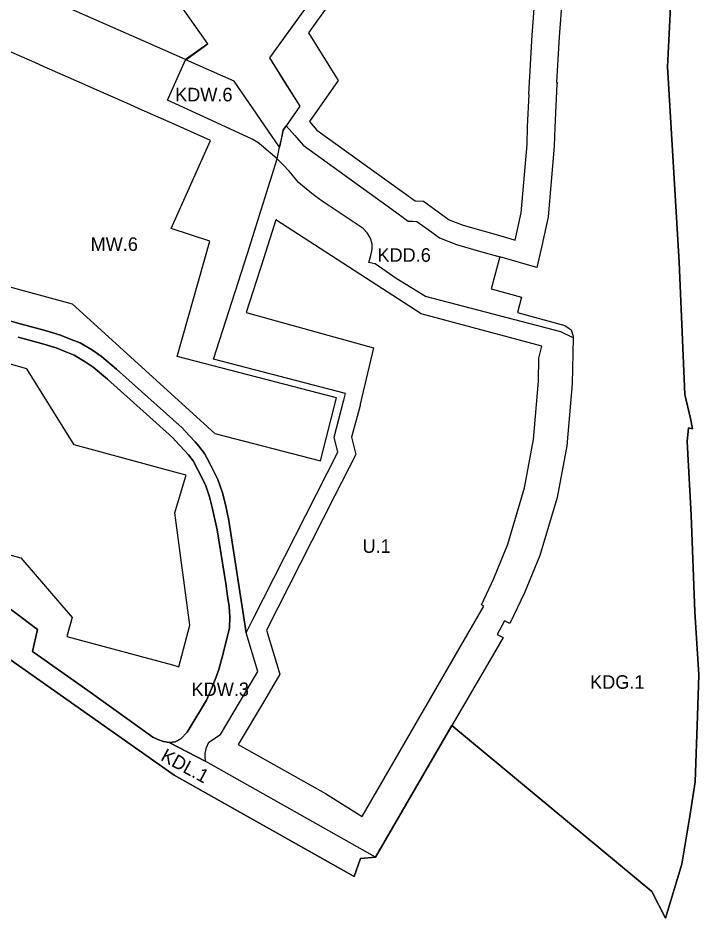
# Model space of a CAD drawing. Extents: x 7432050 to 7433361, y 5551438 to 5552391.
# Drawn here: x 7432993.3 to 7433194.3, y 5551437.6 to 5551703.3 of the extents above; entities that cross this region are included whole.
import ezdxf

# ---------------------------------------------------------------- set-up
doc = ezdxf.new("R2010")
doc.units = 0
for name, color, linetype in [('granica planu', 7, 'Continuous'), ('linie rozgraniczające', 7, 'Continuous'), ('MPZP_Niebyla_Na_Wzgorzach', 7, 'Continuous'), ('nieprzekraczalne linie zabudowy', 7, 'Continuous'), ('oznaczenia przeznaczen', 7, 'Continuous')]:
    doc.layers.add(name, color=color, linetype=linetype)

msp = doc.modelspace()

# ---------------------------------------------------------------- linework, layer by layer
at = {"layer": 'granica planu'}
for p, q in [((7433092.47, 5551449.86), (7433039.39, 5551479.73)), ((7433189.28, 5551453.42), (7433184.41, 5551437.57))]:
    msp.add_line(p, q, dxfattribs=at)
for points in [[(7433186.18, 5551712.56), (7433185.05, 5551688.87), (7433188.47, 5551631.14), (7433190.16, 5551592.1), (7433191.79, 5551585.02), (7433192.43, 5551582.03), (7433191.23, 5551582.31), (7433190.83, 5551578.25), (7433191.96, 5551556.49), (7433193.11, 5551528), (7433194.31, 5551509.38), (7433193.87, 5551497.26), (7433193.22, 5551477.78), (7433191.57, 5551467.67), (7433189.28, 5551453.42)], [(7433039.39, 5551479.73), (7432960, 5551535.68), (7432943.56, 5551546.17), (7432893.1, 5551557.41)], [(7433121.39, 5551494.42), (7433098.78, 5551455.56), (7433094.4, 5551455.09), (7433092.47, 5551449.86)], [(7433184.41, 5551437.57), (7433180.36, 5551445.41), (7433121.39, 5551494.42)]]:
    msp.add_lwpolyline(points, dxfattribs=at)
at = {"layer": 'linie rozgraniczające'}
for p, q in [((7433026.86, 5551698), (7432950.78, 5551731.59)), ((7433154.12, 5551712.23), (7433153.02, 5551697.71)), ((7433042.75, 5551690.98), (7433026.86, 5551698)), ((7433049.29, 5551695.66), (7433042.75, 5551690.98)), ((7433152.31, 5551683.72), (7433151.71, 5551670.92)), ((7433152.6, 5551683.99), (7433152.31, 5551683.72)), ((7433151.71, 5551670.92), (7433151.53, 5551665.42)), ((7433060.99, 5551633.72), (7433069.8, 5551661.73)), ((7433076.05, 5551654.73), (7433074.82, 5551656.24)), ((7433077.82, 5551653.26), (7433076.05, 5551654.73)), ((7433079.38, 5551651.96), (7433077.82, 5551653.26)), ((7433080.94, 5551650.8), (7433079.38, 5551651.96)), ((7433096.32, 5551639.83), (7433095.21, 5551641.09)), ((7433097.34, 5551638.24), (7433096.32, 5551639.83)), ((7433051, 5551602.59), (7433060.99, 5551633.72)), ((7433098.67, 5551630.66), (7433098.65, 5551630.67)), ((7432994.34, 5551612.91), (7432980.9, 5551616.6)), ((7433008.93, 5551608.38), (7433005.84, 5551609.68)), ((7432993.28, 5551609.06), (7433000.17, 5551607.16)), ((7433011.6, 5551607.34), (7433008.93, 5551608.38)), ((7433015.28, 5551605.17), (7433011.6, 5551607.34)), ((7433013.12, 5551601.8), (7433015.46, 5551600.16)), ((7433089.94, 5551592.45), (7433051, 5551602.59)), ((7433089.94, 5551592.45), (7433051, 5551602.59)), ((7433089.47, 5551590.44), (7433089.94, 5551592.45)), ((7433191.79, 5551585.02), (7433190.16, 5551592.1)), ((7433086.61, 5551579.57), (7433089.4, 5551590.14)), ((7433089.4, 5551590.14), (7433089.47, 5551590.44)), ((7433038.92, 5551579.39), (7433040.89, 5551577.29)), ((7433087.7, 5551575.06), (7433086.61, 5551579.57)), ((7433062.58, 5551525.7), (7433087.7, 5551575.06)), ((7433046.44, 5551569.67), (7433048.59, 5551565.44)), ((7433048.59, 5551565.44), (7433049.82, 5551561.88)), ((7433049.82, 5551561.88), (7433050.64, 5551558.74)), ((7433054.53, 5551559.68), (7433053.65, 5551563.05)), ((7433194.31, 5551509.38), (7433193.11, 5551528)), ((7433060.6, 5551521.71), (7433062.58, 5551525.7)), ((7433055.75, 5551523.17), (7433053.59, 5551514.58)), ((7433193.87, 5551497.26), (7433194.31, 5551509.38)), ((7433193.22, 5551477.78), (7433193.87, 5551497.26)), ((7433098.78, 5551455.56), (7433121.39, 5551494.42)), ((7433121.39, 5551494.42), (7433180.36, 5551445.41)), ((7433039.69, 5551489.62), (7433037.91, 5551489.39)), ((7433037.91, 5551489.39), (7433048.73, 5551483.76)), ((7433098.78, 5551455.56), (7433048.73, 5551483.76)), ((7433039.39, 5551479.73), (7433092.47, 5551449.86)), ((7433092.47, 5551449.86), (7433039.39, 5551479.73)), ((7433191.57, 5551467.67), (7433193.22, 5551477.78)), ((7433189.28, 5551453.42), (7433191.57, 5551467.67)), ((7433094.4, 5551455.09), (7433098.78, 5551455.56)), ((7433092.47, 5551449.86), (7433094.4, 5551455.09)), ((7433184.41, 5551437.57), (7433189.28, 5551453.42)), ((7433189.28, 5551453.42), (7433184.41, 5551437.57)), ((7433180.36, 5551445.41), (7433184.41, 5551437.57))]:
    msp.add_line(p, q, dxfattribs=at)
for points in [[(7433081.21, 5551710.55), (7433074.38, 5551701.03), (7433067.54, 5551691.5), (7433071.99, 5551684.37), (7433076.44, 5551677.23), (7433074.46, 5551674.35), (7433072.47, 5551671.47), (7433074.96, 5551668.6), (7433077.45, 5551665.73), (7433088.07, 5551658.07), (7433098.69, 5551650.41), (7433103.59, 5551646.87), (7433108.5, 5551643.33), (7433109.74, 5551643.29), (7433110.97, 5551643.24), (7433114.33, 5551640.82), (7433117.7, 5551638.4), (7433122.77, 5551636.39), (7433129.14, 5551634.58), (7433135.51, 5551632.77)], [(7433190.16, 5551592.1), (7433188.47, 5551631.14), (7433185.05, 5551688.87), (7433186.18, 5551712.56)], [(7433186.18, 5551712.56), (7433185.05, 5551688.87), (7433188.47, 5551631.14), (7433190.16, 5551592.1), (7433191.79, 5551585.02), (7433192.43, 5551582.03), (7433191.23, 5551582.31), (7433190.83, 5551578.25), (7433191.96, 5551556.49), (7433193.11, 5551528), (7433194.31, 5551509.38), (7433193.87, 5551497.26), (7433193.22, 5551477.78), (7433191.57, 5551467.67), (7433189.28, 5551453.42)], [(7433153.02, 5551697.71), (7433152.25, 5551684.29), (7433152.6, 5551683.99)], [(7433069.8, 5551661.73), (7433065.19, 5551665.62), (7433064.12, 5551666.51), (7433062.45, 5551667.48), (7433048.15, 5551674.07), (7433037.43, 5551679.01), (7433042.69, 5551690.94), (7433042.75, 5551690.98)], [(7433069.8, 5551661.73), (7433070.5, 5551665.12), (7433071.02, 5551667.62), (7433071.53, 5551670.11), (7433072.47, 5551671.47)], [(7433151.53, 5551665.42), (7433149.77, 5551644.59), (7433147.89, 5551636.05), (7433146.48, 5551629.66), (7433135.51, 5551632.77)], [(7433074.82, 5551656.24), (7433073.29, 5551658.08), (7433071.54, 5551659.91), (7433069.8, 5551661.73)], [(7433095.21, 5551641.09), (7433083.08, 5551649.19), (7433080.94, 5551650.8)], [(7433097.39, 5551633.18), (7433097.63, 5551634), (7433097.82, 5551635.07), (7433097.78, 5551636.54), (7433097.34, 5551638.24)], [(7433098.65, 5551630.67), (7433096.83, 5551631.11), (7433097.39, 5551633.18)], [(7433157.12, 5551608.89), (7433153.55, 5551610.6), (7433113.55, 5551621.04), (7433104.95, 5551626.37), (7433098.67, 5551630.66)], [(7433135.51, 5551632.77), (7433132.95, 5551623.34), (7433141.95, 5551620.87), (7433140.71, 5551616.3), (7433154.73, 5551612.51), (7433156.54, 5551611.23), (7433157.13, 5551609.38), (7433157.12, 5551608.89), (7433156.87, 5551595.23)], [(7432980.9, 5551616.6), (7432994.34, 5551612.91), (7433001.26, 5551611.01), (7433005.84, 5551609.68), (7433008.93, 5551608.38), (7433011.6, 5551607.34), (7433015.28, 5551605.17), (7433017.89, 5551603.34), (7433022.35, 5551599.63), (7433041.72, 5551582.26), (7433043.83, 5551580.01), (7433045.56, 5551578.11), (7433046.69, 5551576.86), (7433048.33, 5551574.66), (7433049.99, 5551571.51), (7433052.28, 5551567.01), (7433053.65, 5551563.05), (7433054.53, 5551559.68), (7433055.54, 5551554.94), (7433060.6, 5551521.71)], [(7433005.84, 5551609.68), (7433001.26, 5551611.01), (7432994.34, 5551612.91)], [(7433055.75, 5551523.17), (7433055.8, 5551526.46), (7433055.62, 5551529.51), (7433055.14, 5551532.55), (7433054.65, 5551536.34), (7433052.1, 5551552.18), (7433050.64, 5551558.74), (7433049.82, 5551561.88), (7433048.59, 5551565.44), (7433046.44, 5551569.67), (7433044.94, 5551572.52), (7433043.59, 5551574.32), (7433042.6, 5551575.42), (7433040.89, 5551577.29), (7433038.92, 5551579.39), (7433019.73, 5551596.6), (7433015.46, 5551600.16), (7433013.12, 5551601.8), (7433009.84, 5551603.73), (7433007.43, 5551604.68), (7433004.5, 5551605.9), (7433000.17, 5551607.16), (7432993.28, 5551609.06)], [(7433000.17, 5551607.16), (7433004.5, 5551605.9), (7433007.43, 5551604.68), (7433009.84, 5551603.73), (7433013.12, 5551601.8)], [(7433049.99, 5551571.51), (7433048.33, 5551574.66), (7433046.69, 5551576.86), (7433045.56, 5551578.11), (7433043.83, 5551580.01), (7433041.72, 5551582.26), (7433022.35, 5551599.63), (7433017.89, 5551603.34), (7433015.28, 5551605.17)], [(7433015.46, 5551600.16), (7433019.73, 5551596.6), (7433038.92, 5551579.39)], [(7433156.87, 5551595.23), (7433155.32, 5551577), (7433152.41, 5551561.71), (7433147.28, 5551544.57), (7433142.75, 5551533.54), (7433138.51, 5551524.5), (7433136.93, 5551525.32), (7433134.74, 5551521.23), (7433136.5, 5551520.39), (7433132.55, 5551513.6), (7433121.39, 5551494.42)], [(7433193.11, 5551528), (7433191.96, 5551556.49), (7433190.83, 5551578.25), (7433191.23, 5551582.31), (7433192.43, 5551582.03), (7433191.79, 5551585.02)], [(7433040.89, 5551577.29), (7433042.6, 5551575.42), (7433043.59, 5551574.32), (7433044.94, 5551572.52), (7433046.44, 5551569.67)], [(7433053.65, 5551563.05), (7433052.28, 5551567.01), (7433049.99, 5551571.51)], [(7433060.6, 5551521.71), (7433055.54, 5551554.94), (7433054.53, 5551559.68)], [(7433039.39, 5551479.73), (7432960, 5551535.68), (7432943.56, 5551546.17), (7432893.1, 5551557.41)], [(7433050.64, 5551558.74), (7433052.1, 5551552.18), (7433054.65, 5551536.34)], [(7432943.56, 5551546.17), (7432960, 5551535.68), (7433039.39, 5551479.73)], [(7432957.13, 5551544.64), (7432960.96, 5551542.08), (7432969.46, 5551544.99), (7432999.04, 5551522.76)], [(7432999.04, 5551522.76), (7432969.46, 5551544.99), (7432960.96, 5551542.08), (7432957.13, 5551544.64)], [(7433054.65, 5551536.34), (7433055.14, 5551532.55), (7433055.62, 5551529.51), (7433055.8, 5551526.46), (7433055.75, 5551523.17)], [(7432999.04, 5551522.76), (7432997.6, 5551516.25), (7433013.93, 5551504.72), (7433033.12, 5551490.99)], [(7433033.12, 5551490.99), (7433013.93, 5551504.72), (7432997.6, 5551516.25), (7432999.04, 5551522.76)], [(7433037.91, 5551489.39), (7433039.69, 5551489.62), (7433041.38, 5551490.42), (7433043.17, 5551492.4), (7433043.67, 5551493.23), (7433048.89, 5551501.92), (7433050.35, 5551505.27), (7433051.72, 5551508.51), (7433052.54, 5551510.94), (7433053.59, 5551514.58), (7433055.75, 5551523.17)], [(7433048.73, 5551483.76), (7433048.51, 5551484.89), (7433048.52, 5551486.14), (7433048.96, 5551487.91), (7433049.57, 5551489.5), (7433053.08, 5551491.73), (7433060.85, 5551504.87), (7433064.09, 5551510.36), (7433060.6, 5551521.71)], [(7433053.59, 5551514.58), (7433052.54, 5551510.94), (7433051.72, 5551508.51)], [(7433051.72, 5551508.51), (7433050.35, 5551505.27), (7433048.89, 5551501.92)], [(7433048.89, 5551501.92), (7433043.67, 5551493.23), (7433043.17, 5551492.4)], [(7433121.39, 5551494.42), (7433098.78, 5551455.56), (7433094.4, 5551455.09), (7433092.47, 5551449.86)], [(7433184.41, 5551437.57), (7433180.36, 5551445.41), (7433121.39, 5551494.42)], [(7433033.12, 5551490.99), (7433034.51, 5551490.31), (7433036.18, 5551489.67), (7433037.91, 5551489.39)], [(7433048.73, 5551483.76), (7433037.91, 5551489.39), (7433036.18, 5551489.67), (7433034.51, 5551490.31), (7433033.12, 5551490.99)], [(7433043.17, 5551492.4), (7433041.38, 5551490.42), (7433039.69, 5551489.62)]]:
    msp.add_lwpolyline(points, dxfattribs=at)
at = {"layer": 'MPZP_Niebyla_Na_Wzgorzach'}
msp.add_lwpolyline([(7432977.09, 5551884.32), (7433000.73, 5551864.23), (7433015.69, 5551852.7), (7433021.07, 5551848.25), (7433033.09, 5551838.49), (7433033.6, 5551838.07), (7433043.07, 5551830.37), (7433042.68, 5551829.88), (7433032.93, 5551817.5), (7433032.85, 5551817.27), (7433029.29, 5551807.1), (7433022.82, 5551795.73), (7433097.26, 5551736.86), (7433100.01, 5551734.68), (7433094.28, 5551727.25), (7433081.21, 5551710.55), (7433067.54, 5551691.5), (7433076.44, 5551677.23), (7433071.53, 5551670.11), (7433070.5, 5551665.12), (7433057.06, 5551684.66), (7433042.84, 5551690.94), (7433049.29, 5551695.66), (7432912.36, 5551889.43)], dxfattribs=at)
at = {"layer": 'nieprzekraczalne linie zabudowy'}
for p, q in [((7433079.01, 5551698.91), (7433087.78, 5551684.86)), ((7433087.78, 5551684.86), (7433079.37, 5551672.67)), ((7433038.45, 5551641.17), (7433050.13, 5551667.12)), ((7433112.31, 5551615.92), (7433069.36, 5551643.67)), ((7433049.93, 5551637.38), (7433038.45, 5551641.17)), ((7433040.26, 5551603.37), (7433049.93, 5551637.38)), ((7432968.76, 5551630.02), (7433009.24, 5551618.85)), ((7433060.67, 5551616.36), (7433098.2, 5551605.85)), ((7433146.91, 5551596.08), (7433147.01, 5551602.89)), ((7433145.5, 5551578.87), (7433146.91, 5551596.08)), ((7433142.83, 5551564.58), (7433145.5, 5551578.87)), ((7433137.84, 5551547.91), (7433142.83, 5551564.58)), ((7433086.71, 5551562.1), (7433066.61, 5551522.59)), ((7433133.7, 5551537.79), (7433137.84, 5551547.91)), ((7433130.08, 5551530.06), (7433133.7, 5551537.79))]:
    msp.add_line(p, q, dxfattribs=at)
for points in [[(7433108.52, 5551737.56), (7433105.97, 5551734.21), (7433103.97, 5551731.62), (7433098.23, 5551724.18), (7433085.21, 5551707.55), (7433079.01, 5551698.91)], [(7433140.07, 5551637.71), (7433141.84, 5551645.79), (7433143.54, 5551665.89), (7433143.72, 5551671.24), (7433144.16, 5551680.69), (7433144.04, 5551680.79), (7433145.04, 5551698.24), (7433145.82, 5551708.55), (7433108.52, 5551737.56)], [(7433050.13, 5551667.12), (7433040.22, 5551671.58), (7433029.07, 5551676.49), (7433026.25, 5551677.77), (7433015.03, 5551682.69), (7433012.26, 5551683.94), (7433001.05, 5551688.83), (7432998.21, 5551690.1), (7432987.31, 5551694.87), (7432977.31, 5551699.38)], [(7433079.37, 5551672.67), (7433081.53, 5551670.19), (7433102.2, 5551655.28), (7433110.54, 5551649.26), (7433113, 5551649.17), (7433120.6, 5551643.7), (7433124.7, 5551642.08), (7433137.15, 5551638.54), (7433140.07, 5551637.71)], [(7433069.36, 5551643.67), (7433065.75, 5551632.21), (7433060.67, 5551616.36)], [(7433009.24, 5551618.85), (7433051.35, 5551580.61), (7433082.53, 5551572.49)], [(7433147.01, 5551602.89), (7433147.95, 5551606.43), (7433112.31, 5551615.92)], [(7433098.2, 5551605.85), (7433094.33, 5551589.25), (7433094.24, 5551588.88), (7433091.77, 5551579.51), (7433092.99, 5551574.44), (7433086.71, 5551562.1)], [(7433082.53, 5551572.49), (7433087.32, 5551591.16), (7433040.26, 5551603.37)], [(7433058.3, 5551488.77), (7433084.08, 5551474.29), (7433094.84, 5551467.54), (7433103.58, 5551482.47), (7433130.84, 5551529.62), (7433130.08, 5551530.06)], [(7433066.61, 5551522.59), (7433070.6, 5551509.59), (7433066.02, 5551501.82), (7433058.3, 5551488.77)]]:
    msp.add_lwpolyline(points, dxfattribs=at)
msp.add_lwpolyline([(7432913.28, 5551570.92), (7432944.25, 5551562.35), (7432963.1, 5551552.22), (7432994.07, 5551543.89), (7433009.28, 5551526.25), (7433007.73, 5551520.67), (7433038.85, 5551512.28), (7433040.78, 5551511.76), (7433043.99, 5551523.99), (7433039.6, 5551557.15), (7433042.76, 5551567.67), (7433042.94, 5551568.29), (7433040.67, 5551568.91), (7433009.86, 5551577.26), (7432995.86, 5551599.73), (7432965.34, 5551608.36), (7432962.07, 5551597.14), (7432916.36, 5551582.2)], close=True, dxfattribs=at)

# ---------------------------------------------------------------- texts
at = {"layer": 'oznaczenia przeznaczen'}
for s, p in [('KDW.6', (7433039.66, 5551678.66)), ('MW.6', (7433014.71, 5551634.51)), ('KDD.6', (7433099.39, 5551631.3)), ('U.1', (7433094.98, 5551545.37)), ('KDG.1', (7433162.16, 5551505.24)), ('KDW.3', (7433044.52, 5551503.09))]:
    msp.add_text(s, height=4, dxfattribs=at).set_placement(p)
msp.add_text('KDL.1', height=4, rotation=331.5468, dxfattribs=at).set_placement((7433035.12, 5551484.29))

doc.saveas('drawing.dxf')
